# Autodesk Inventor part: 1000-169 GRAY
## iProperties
Created: 2007-03
Part Number: 1000-169 GRAY
Document SubType Name: Modeling
Designer: Andy Moles
Density: 1 g/cm^3
Mass: 11.295 g
Surface Area: 76.161 cm^2
Volume: 11.295 cm^3
Author: Andy Moles
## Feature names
1. Base1
